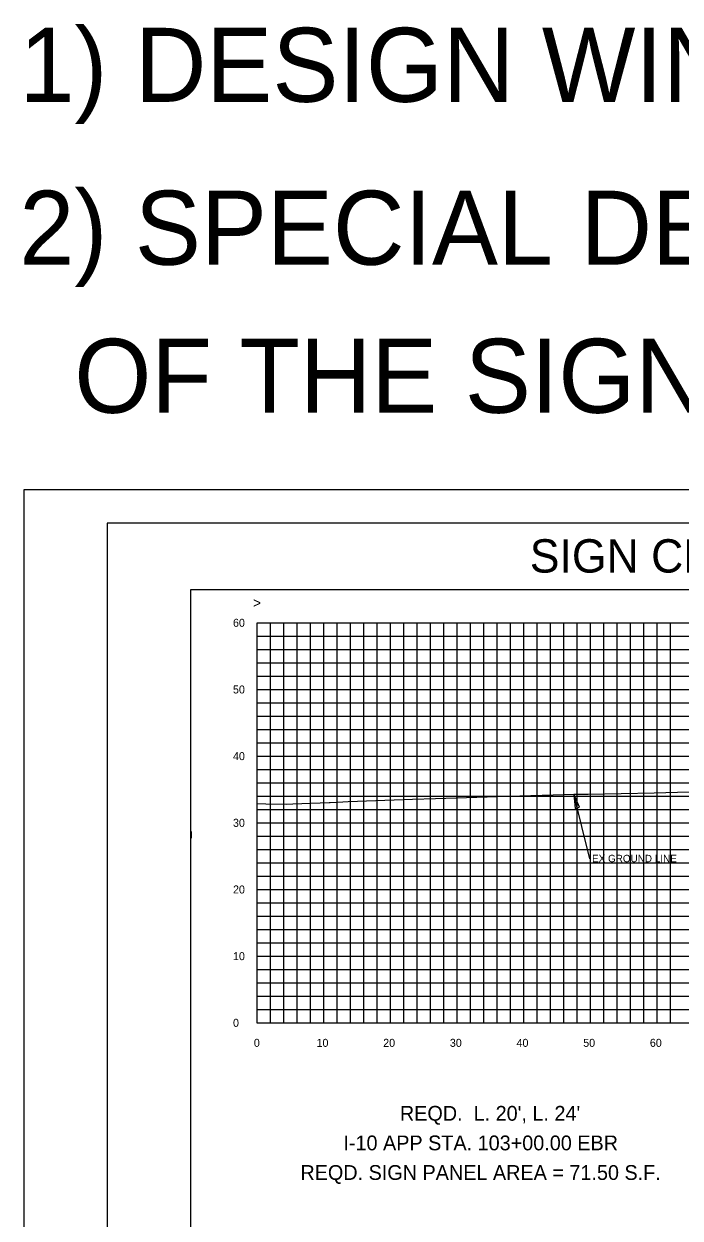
# Model space of a CAD drawing. Extents: x 2193008 to 2198143, y 1236112 to 1237864.
# Drawn here: x 2194857.9 to 2194956.3, y 1237228.8 to 1237407.9 of the extents above; entities that cross this region are included whole.
import ezdxf

# ---------------------------------------------------------------- set-up
doc = ezdxf.new("R2010")
doc.units = 0
for name, color, linetype in [('2', 7, 'Continuous'), ('3', 7, 'Continuous'), ('31', 7, 'Continuous'), ('60', 7, 'Continuous'), ('ANNO-SHT', 7, 'Continuous'), ('AXIS', 7, 'Continuous'), ('GSDIMS', 7, 'Continuous'), ('Level 55', 7, 'Continuous'), ('LIMT-CSLINE', 7, 'Continuous'), ('M-ROADS', 7, 'Continuous'), ('SHT-BNDRY', 7, 'Continuous')]:
    doc.layers.add(name, color=color, linetype=linetype)

msp = doc.modelspace()

# ---------------------------------------------------------------- linework, layer by layer
msp.add_lwpolyline([(2194882.86, 1237133.05), (2195182.86, 1237133.05), (2195182.86, 1237323.05), (2194882.86, 1237323.05)], close=True)
at = {"layer": '2'}
msp.add_lwpolyline([(2194882.97, 1237286.82), (2194882.96, 1237285.82)], dxfattribs=at)
msp.add_lwpolyline([(2194882.97, 1237286.82), (2194882.96, 1237285.82)], dxfattribs=at)
at = {"layer": '3'}
msp.add_line((2194942.76, 1237282.7), (2194940.36, 1237292.39), dxfattribs=at)
at = {"layer": '60'}
for p, q in [((2194892.86, 1237258.11), (2194892.86, 1237318.11)), ((2194892.86, 1237258.05), (2194892.86, 1237258.11)), ((2194892.86, 1237258.11), (2195022.86, 1237258.11)), ((2194902.86, 1237258.05), (2194902.86, 1237258.11)), ((2194912.86, 1237258.05), (2194912.86, 1237258.11)), ((2194922.86, 1237258.05), (2194922.86, 1237258.11)), ((2194932.86, 1237258.05), (2194932.86, 1237258.11)), ((2194942.86, 1237258.05), (2194942.86, 1237258.11)), ((2194952.86, 1237258.05), (2194952.86, 1237258.11))]:
    msp.add_line(p, q, dxfattribs=at)
at = {"layer": 'AXIS'}
msp.add_line((2194882.86, 1237243.04), (2194882.86, 1237243.05), dxfattribs=at)
at = {"layer": 'GSDIMS'}
msp.add_lwpolyline([(2194940.36, 1237292.39), (2194940.53, 1237290.25), (2194941.21, 1237290.44)], close=True, dxfattribs=at)
at = {"layer": 'M-ROADS'}
for p, q in [((2194892.86, 1237318.11), (2195022.86, 1237318.11)), ((2194894.86, 1237258.11), (2194894.86, 1237318.11)), ((2194896.86, 1237258.11), (2194896.86, 1237318.11)), ((2194898.86, 1237258.11), (2194898.86, 1237318.11)), ((2194900.86, 1237258.11), (2194900.86, 1237318.11)), ((2194902.86, 1237258.11), (2194902.86, 1237318.11)), ((2194904.86, 1237258.11), (2194904.86, 1237318.11)), ((2194906.86, 1237258.11), (2194906.86, 1237318.11)), ((2194908.86, 1237258.11), (2194908.86, 1237318.11)), ((2194910.86, 1237258.11), (2194910.86, 1237318.11)), ((2194912.86, 1237258.11), (2194912.86, 1237318.11)), ((2194914.86, 1237258.11), (2194914.86, 1237318.11)), ((2194916.86, 1237258.11), (2194916.86, 1237318.11)), ((2194918.86, 1237258.11), (2194918.86, 1237318.11)), ((2194920.86, 1237258.11), (2194920.86, 1237318.11)), ((2194922.86, 1237258.11), (2194922.86, 1237318.11)), ((2194924.86, 1237258.11), (2194924.86, 1237318.11)), ((2194926.86, 1237258.11), (2194926.86, 1237318.11)), ((2194928.86, 1237258.11), (2194928.86, 1237318.11)), ((2194930.86, 1237258.11), (2194930.86, 1237318.11)), ((2194932.86, 1237258.11), (2194932.86, 1237318.11)), ((2194934.86, 1237258.11), (2194934.86, 1237318.11)), ((2194936.86, 1237258.11), (2194936.86, 1237318.11)), ((2194938.86, 1237258.11), (2194938.86, 1237318.11)), ((2194940.86, 1237258.11), (2194940.86, 1237318.11)), ((2194942.86, 1237258.11), (2194942.86, 1237318.11)), ((2194944.86, 1237258.11), (2194944.86, 1237318.11)), ((2194946.86, 1237258.11), (2194946.86, 1237318.11)), ((2194948.86, 1237258.11), (2194948.86, 1237318.11)), ((2194950.86, 1237258.11), (2194950.86, 1237318.11)), ((2194952.86, 1237258.11), (2194952.86, 1237318.11)), ((2194954.86, 1237258.11), (2194954.86, 1237318.11)), ((2194892.86, 1237316.11), (2195022.86, 1237316.11)), ((2194892.86, 1237314.11), (2195022.86, 1237314.11)), ((2194892.86, 1237312.11), (2195022.86, 1237312.11)), ((2194892.86, 1237310.11), (2195022.86, 1237310.11)), ((2194892.86, 1237308.11), (2195022.86, 1237308.11)), ((2194892.86, 1237306.11), (2195022.86, 1237306.11)), ((2194892.86, 1237304.11), (2195022.86, 1237304.11)), ((2194892.86, 1237302.11), (2195022.86, 1237302.11)), ((2194892.86, 1237300.11), (2195022.86, 1237300.11)), ((2194892.86, 1237298.11), (2195022.86, 1237298.11)), ((2194892.86, 1237296.11), (2195022.86, 1237296.11)), ((2194892.86, 1237294.11), (2195022.86, 1237294.11)), ((2194892.86, 1237292.11), (2195022.86, 1237292.11)), ((2194892.86, 1237290.11), (2195022.86, 1237290.11)), ((2194892.86, 1237288.11), (2195022.86, 1237288.11)), ((2194892.86, 1237286.11), (2195022.86, 1237286.11)), ((2194892.86, 1237284.11), (2195022.86, 1237284.11)), ((2194892.86, 1237282.11), (2195022.86, 1237282.11)), ((2194892.86, 1237280.11), (2195022.86, 1237280.11)), ((2194892.86, 1237278.11), (2195022.86, 1237278.11)), ((2194892.86, 1237276.11), (2195022.86, 1237276.11)), ((2194892.86, 1237274.11), (2195022.86, 1237274.11)), ((2194892.86, 1237272.11), (2195022.86, 1237272.11)), ((2194892.86, 1237270.11), (2195022.86, 1237270.11)), ((2194892.86, 1237268.11), (2195022.86, 1237268.11)), ((2194892.86, 1237266.11), (2195022.86, 1237266.11)), ((2194892.86, 1237264.11), (2195022.86, 1237264.11)), ((2194892.86, 1237262.11), (2195022.86, 1237262.11)), ((2194892.86, 1237260.11), (2195022.86, 1237260.11)), ((2194892.86, 1237258.11), (2195022.86, 1237258.11))]:
    msp.add_line(p, q, dxfattribs=at)
msp.add_lwpolyline([(2194857.86, 1237118.04), (2195197.86, 1237118.04), (2195197.86, 1237338.04), (2194857.86, 1237338.04)], close=True, dxfattribs=at)
msp.add_lwpolyline([(2194892.86, 1237291), (2194894.14, 1237290.98), (2194897.26, 1237290.93), (2194898.19, 1237290.96), (2194903.64, 1237291.16), (2194903.81, 1237291.17), (2194904.89, 1237291.23), (2194906.5, 1237291.29), (2194916.17, 1237291.64), (2194919.61, 1237291.75), (2194928.88, 1237292.05), (2194937.25, 1237292.29), (2194940.36, 1237292.39), (2194942.49, 1237292.43), (2194952.38, 1237292.62), (2194957.64, 1237292.74)], dxfattribs=at)
at = {"layer": 'SHT-BNDRY'}
msp.add_lwpolyline([(2194870.36, 1237123.04), (2195192.86, 1237123.04), (2195192.86, 1237333.04), (2194870.36, 1237333.04)], close=True, dxfattribs=at)

# ---------------------------------------------------------------- texts
at = {"layer": '31'}
for s, p in [('60', (2194889.23, 1237317.51)), ('50', (2194889.23, 1237307.51)), ('40', (2194889.23, 1237297.51)), ('30', (2194889.23, 1237287.51)), ('20', (2194889.23, 1237277.51)), ('10', (2194889.23, 1237267.51)), ('0', (2194889.23, 1237257.51))]:
    msp.add_text(s, height=1.2, dxfattribs=at).set_placement(p)
at = {"layer": '60'}
msp.add_text('>', height=1.5, dxfattribs=at).set_placement((2194892.25, 1237320.36))
at = {"layer": 'ANNO-SHT'}
msp.add_text('              SIGN CROSS SECTIONS               ', height=4.9995, rotation=360, dxfattribs=at).set_placement((2194907.74, 1237325.64))
at = {"layer": 'Level 55'}
for s, height, p in [('1) DESIGN WIND VELOCITY 100 MPH', 11.1046, (2194857.18, 1237396.24)), ('2) SPECIAL DESIGN POSTS ARE NEEDED BECAUSE THE DISTANCE BETWEEN THE BOTTOM OF THE CENTER', 11.1046, (2194857.18, 1237371.81)), ("  OF THE SIGN AND TOP OF THE EXISTING GROUND EXCEEDS 14' - ALDOT 1202", 11.1046, (2194857.18, 1237349.6)), ('EX GROUND LINE', 1.1105, (2194943.09, 1237282.2)), (" REQD.  L. 20', L. 24'", 2.2209, (2194913.44, 1237243.43)), ('I-10 APP STA. 103+00.00 EBR', 2.2209, (2194905.79, 1237238.99)), ('REQD. SIGN PANEL AREA = 71.50 S.F.', 2.2209, (2194899.34, 1237234.55))]:
    msp.add_text(s, height=height, dxfattribs=at).set_placement(p)
at = {"layer": 'LIMT-CSLINE'}
for s, p in [('0', (2194892.36, 1237254.51)), ('10', (2194901.76, 1237254.51)), ('20', (2194911.76, 1237254.51)), ('30', (2194921.76, 1237254.51)), ('40', (2194931.76, 1237254.51)), ('50', (2194941.76, 1237254.51)), ('60', (2194951.76, 1237254.51))]:
    msp.add_text(s, height=1.2, dxfattribs=at).set_placement(p)

doc.saveas('drawing.dxf')
